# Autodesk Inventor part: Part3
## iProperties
Shininess: 77.0
Angle Display Precision: 2
Document Length Units: 11269
Document Angle Units: 11279
Document Time Units: 11290
Document Mass Units: 11283
Document Length Units Precision: 3
Document Angle Units Precision: 2
Compacted: True
Created: 2001-12
Part Number: Part3
Document SubType Name: Modeling
Designer: Renu Muthoo
Density: 1 g/cm^3
Density: 0.0
Volumn: 0.0
Area: 0.0
PropertySet Name: Model Information
Control State: 0
Master: False
Checked Out: False
Author: Renu Muthoo
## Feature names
1. Revolution2
2. Extrusion1
